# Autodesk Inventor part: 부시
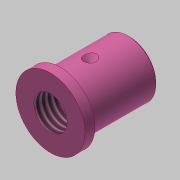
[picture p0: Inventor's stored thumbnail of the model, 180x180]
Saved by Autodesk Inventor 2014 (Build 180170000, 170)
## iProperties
Created: 2019-04
Part Number: 부시
Material: 강철, 연강
Document SubType Name: Modeling
Designer: mduedu
Density: 1 g/cm^3
Appearance: Pink
Author: mduedu
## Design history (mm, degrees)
sketch "스케치1"
  geometry: L1 (0, 0)-(3, 0); L2 (3, 0)-(3, 10.5); L3 (3, 10.5)-(0, 10.5); L4 (0, 10.5)-(0, 0); L5 (3, 0)-(24, 0); L6 (24, 0)-(24, 8.5); L7 (24, 8.5)-(3, 8.5); L8 (3, 8.5)-(3, 0)
  constraints: 16 end point, 4 parallel, 2 horizontal, 2 perpendicular
  dimensions: "d0" = 3 distance of L2.end L3.end; "d2" = 24 distance between parallel lines of L6 L4; "d3" = 17 diameter of L7 L5; "d4" = 21 diameter of L3 L1
revolve "회전1" sketch "스케치1" stored, may be unused: angle "d5" = 90 deg
sketch "스케치2"
  geometry: L1 (3, 8.5)-(24, 8.5) reference; L2 (12, 8.5)-(12, 6.5); L3 (12, 6.5)-(14, 8.5); L4 (0, -10.5)-(0, 10.5) reference; 1 further point
  constraints: 4 end point, 2 point on line, 1 perpendicular
  dimensions: "d6" = 12 distance from line of L2.start L4; "d7" = 2 distance of L2.start L3.end; "d8" = 45 deg angle of L3 L2
revolve "회전2" sketch "스케치2" stored, may be unused: angle "d9" = 90 deg
hole "구멍1" diameter "d12" = 10.106; stored, may be unused: countersink angle "d16" = 90 deg, drill point angle "d18" = 118 deg; dims "d10" = 10, "d11" = 10, "d13" = 39, "d14" = 4, "d15" = 2, "d17" = 8
chamfer "모따기1" distance "d19" = 0.5; stored, may be unused: second distance "d20" = 2, angle "d21" = 45 deg
node "작업점1"
  node "작업 평면1"
  node "작업축1"
node "솔리드1"
